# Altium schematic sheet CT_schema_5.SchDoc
size 143 x 123 mm
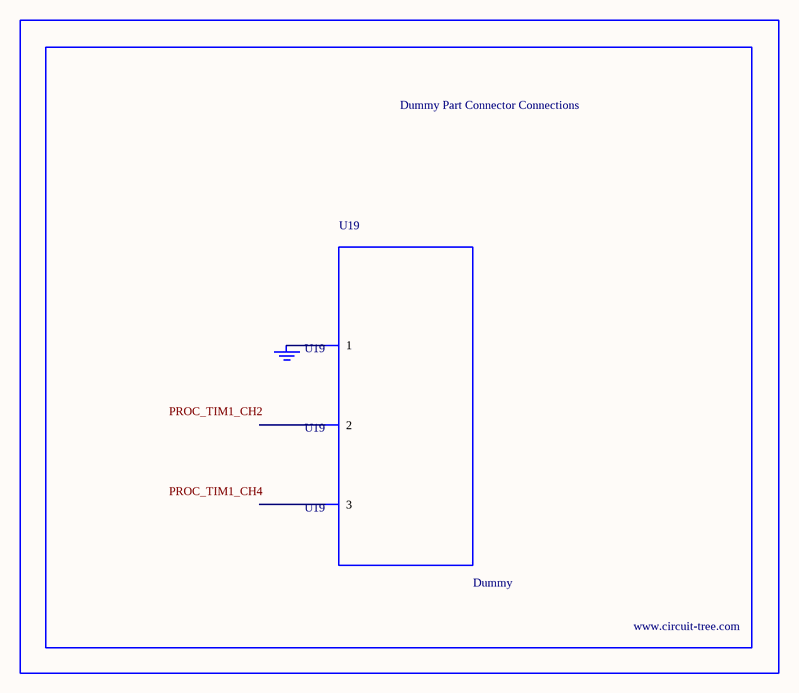
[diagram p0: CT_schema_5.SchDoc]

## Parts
BORDER4  (no value)
GND_INSTANCE_4_0  (no value)
U19  Dummy  [DUMMY_PACKAGE_166]

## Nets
NetGND_INSTANCE_4_0_0: GND_INSTANCE_4_0.0(GND) U19.1

Not connected (* = marked no-connect by the designer): U19 2 3

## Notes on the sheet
- Labels drawn without touching a wire or pin: PROC_TIM1_CH2, PROC_TIM1_CH4

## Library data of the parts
BORDER4 = BORDER_PAGE4
GND_INSTANCE_4_0 = GND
